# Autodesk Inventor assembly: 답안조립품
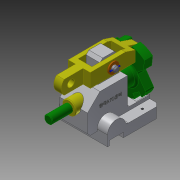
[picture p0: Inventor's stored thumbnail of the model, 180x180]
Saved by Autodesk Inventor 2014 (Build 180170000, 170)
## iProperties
Created: 2016-11
Part Number: 답안조립품
Document SubType Name: Assembly
Designer: user
Author: user
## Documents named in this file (8)
- C:\Users\user\Desktop\461108v1004\답안조립품.iam
- C:\Users\user\Desktop\461108v1004\본체.ipt
- C:\Users\user\Desktop\461108v1004\부시.ipt
- C:\Users\user\Desktop\461108v1004\분할대.ipt
- C:\Users\user\Desktop\461108v1004\분할축.ipt
- C:\Users\user\Desktop\461108v1004\와셔.ipt
- C:\Users\user\Desktop\461108v1004\원통형핀.ipt
- C:\Users\user\Desktop\461108v1004\클레비스핀.ipt
